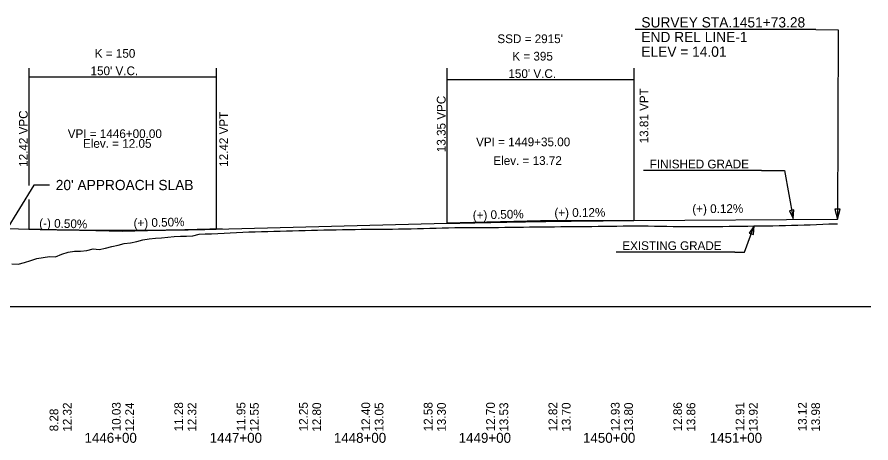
# Model space of a CAD drawing. Extents: x 2360994 to 2383826, y 330623 to 403123.
# Drawn here: x 2369741 to 2370426, y 376763 to 377105 of the extents above; entities that cross this region are included whole.
import ezdxf

# ---------------------------------------------------------------- set-up
doc = ezdxf.new("R2010")
doc.units = 0
for name, color, linetype in [('RD_DDB_GradeTX', 7, 'Continuous'), ('RD_DDB_Profile_EX', 7, 'Continuous'), ('RD_DDB_Profile_Lbl', 7, 'Continuous'), ('RD_DDB_Profile_PR', 7, 'Continuous'), ('RD_DDB_StaTX', 7, 'Continuous'), ('RD_DDB_StripGrade', 7, 'Continuous'), ('RD_DDB_VCLbl', 7, 'Continuous'), ('RD_GPK_Profile_Cell', 7, 'Continuous'), ('RD_TX_Profile', 7, 'Continuous')]:
    doc.layers.add(name, color=color, linetype=linetype)

msp = doc.modelspace()

# ---------------------------------------------------------------- linework, layer by layer
at = {"layer": 'RD_DDB_GradeTX'}
for p, q in [((2370160.57, 376941.5), (2370085.57, 376939.63)), ((2370235.57, 376941.95), (2370160.57, 376941.5)), ((2369825.57, 376933.13), (2369750.57, 376935)), ((2369905.54, 376935.13), (2369825.57, 376933.13))]:
    msp.add_line(p, q, dxfattribs=at)
at = {"layer": 'RD_DDB_Profile_EX'}
for points in [[(2369826.95, 376923.34), (2369831.95, 376923.97), (2369836.95, 376924.99), (2369841.95, 376926.25), (2369846.95, 376927.05), (2369851.95, 376927.63), (2369856.95, 376928.04), (2369861.95, 376928.42), (2369866.95, 376929.06), (2369871.95, 376929.37), (2369876.95, 376929.28), (2369881.95, 376929.67), (2369886.95, 376930.96), (2369891.95, 376931.25), (2369896.95, 376931.23), (2369901.95, 376931.53), (2369906.95, 376931.73), (2369911.95, 376931.98), (2369916.95, 376932.24), (2369921.95, 376932.46), (2369926.95, 376932.68), (2369931.95, 376932.85), (2369936.95, 376933), (2369941.95, 376933.16), (2369946.95, 376933.3), (2369951.95, 376933.44), (2369956.95, 376933.58), (2369961.95, 376933.71), (2369966.95, 376933.84), (2369971.95, 376934), (2369976.95, 376934.16), (2369981.95, 376934.24), (2369986.95, 376934.31), (2369991.95, 376934.41), (2369996.95, 376934.5), (2370001.95, 376934.59), (2370006.95, 376934.68), (2370011.95, 376934.76), (2370016.95, 376934.82), (2370021.95, 376934.87), (2370026.95, 376934.9), (2370031.95, 376934.96), (2370036.95, 376935.01), (2370041.95, 376935.07), (2370046.95, 376935.15), (2370051.95, 376935.23), (2370056.95, 376935.33), (2370061.95, 376935.42), (2370066.95, 376935.56), (2370071.95, 376935.72), (2370076.95, 376935.83), (2370081.95, 376935.96), (2370086.95, 376936.09), (2370091.95, 376936.17), (2370096.95, 376936.22), (2370101.95, 376936.25), (2370106.95, 376936.26), (2370111.95, 376936.28), (2370116.95, 376936.3), (2370121.95, 376936.36), (2370126.95, 376936.41), (2370131.95, 376936.58), (2370136.95, 376936.6), (2370141.95, 376936.63), (2370146.95, 376936.66), (2370151.95, 376936.71), (2370156.95, 376936.76), (2370161.95, 376936.82), (2370166.95, 376936.89), (2370171.95, 376936.94), (2370176.95, 376936.98), (2370181.95, 376937.02), (2370186.95, 376937.06), (2370191.95, 376937.08), (2370196.95, 376937.12), (2370201.95, 376937.17), (2370206.95, 376937.22), (2370211.95, 376937.3), (2370216.95, 376937.39), (2370221.95, 376937.48), (2370226.95, 376937.55), (2370231.95, 376937.6), (2370236.95, 376937.59), (2370241.95, 376937.56), (2370246.95, 376937.49), (2370251.95, 376937.4), (2370256.95, 376937.31), (2370261.95, 376937.25), (2370266.95, 376937.18), (2370271.95, 376937.16), (2370276.95, 376937.19), (2370281.95, 376937.21), (2370286.95, 376937.17), (2370291.95, 376937.17), (2370296.95, 376937.12), (2370301.95, 376937.17), (2370306.95, 376937.21), (2370311.95, 376937.25), (2370316.95, 376937.31), (2370321.95, 376937.38), (2370326.95, 376937.45)], [(2370326.95, 376937.45), (2370331.95, 376937.52), (2370336.95, 376937.56), (2370341.95, 376937.59), (2370346.95, 376937.68), (2370351.95, 376937.8), (2370356.95, 376937.91), (2370361.95, 376938.05), (2370366.95, 376938.18), (2370371.95, 376938.32), (2370376.95, 376938.54), (2370381.95, 376938.7), (2370386.95, 376938.91), (2370391.95, 376939.11), (2370396.95, 376939.22), (2370398.85, 376939.28)], [(2369736.95, 376907.13), (2369741.95, 376906.91), (2369746.95, 376908.24), (2369751.95, 376909.8), (2369756.95, 376911.33), (2369761.95, 376912.3), (2369766.95, 376913.01), (2369771.95, 376912.81), (2369776.95, 376914.82), (2369781.95, 376916.56), (2369786.95, 376917.32), (2369791.95, 376917.17), (2369796.95, 376917.85), (2369801.95, 376919.15), (2369806.95, 376918.63), (2369811.95, 376919.8), (2369816.95, 376921.09), (2369821.95, 376922.2), (2369826.95, 376923.34)]]:
    msp.add_lwpolyline(points, dxfattribs=at)
at = {"layer": 'RD_DDB_Profile_PR'}
for p, q in [((2368940.57, 376955.25), (2369750.57, 376935)), ((2369900.57, 376935), (2370085.57, 376939.63)), ((2370235.57, 376941.95), (2370398.85, 376942.93))]:
    msp.add_line(p, q, dxfattribs=at)
for points in [[(2370085.57, 376939.63), (2370088.57, 376939.7), (2370091.57, 376939.77), (2370094.57, 376939.85), (2370097.57, 376939.92), (2370100.57, 376939.99), (2370103.57, 376940.06), (2370106.57, 376940.12), (2370109.57, 376940.19), (2370112.57, 376940.25), (2370115.57, 376940.32), (2370118.57, 376940.38), (2370121.57, 376940.44), (2370124.57, 376940.5), (2370127.57, 376940.56), (2370130.57, 376940.62), (2370133.57, 376940.68), (2370136.57, 376940.74), (2370139.57, 376940.79), (2370142.57, 376940.85), (2370145.57, 376940.9), (2370148.57, 376940.95), (2370151.57, 376941), (2370154.57, 376941.05), (2370157.57, 376941.1), (2370160.57, 376941.14), (2370163.57, 376941.19), (2370166.57, 376941.24), (2370169.57, 376941.28), (2370172.57, 376941.32), (2370175.57, 376941.36), (2370178.57, 376941.4), (2370181.57, 376941.44), (2370184.57, 376941.48), (2370187.57, 376941.52), (2370190.57, 376941.55), (2370193.57, 376941.59), (2370196.57, 376941.62), (2370199.57, 376941.65), (2370202.57, 376941.68), (2370205.57, 376941.71), (2370208.57, 376941.74), (2370211.57, 376941.77), (2370214.57, 376941.8), (2370217.57, 376941.82), (2370220.57, 376941.85), (2370223.57, 376941.87), (2370226.57, 376941.89), (2370229.57, 376941.91), (2370232.57, 376941.93), (2370235.57, 376941.95)], [(2369750.57, 376935), (2369753.57, 376934.93), (2369756.57, 376934.86), (2369759.57, 376934.79), (2369762.57, 376934.72), (2369765.57, 376934.66), (2369768.57, 376934.6), (2369771.57, 376934.55), (2369774.57, 376934.5), (2369777.57, 376934.45), (2369780.57, 376934.4), (2369783.57, 376934.36), (2369786.57, 376934.32), (2369789.57, 376934.28), (2369792.57, 376934.24), (2369795.57, 376934.21), (2369798.57, 376934.18), (2369801.57, 376934.16), (2369804.57, 376934.14), (2369807.57, 376934.12), (2369810.57, 376934.1), (2369813.57, 376934.09), (2369816.57, 376934.08), (2369819.57, 376934.07), (2369822.57, 376934.06), (2369825.57, 376934.06), (2369828.57, 376934.06), (2369831.57, 376934.07), (2369834.57, 376934.08), (2369837.57, 376934.09), (2369840.57, 376934.1), (2369843.57, 376934.12), (2369846.57, 376934.14), (2369849.57, 376934.16), (2369852.57, 376934.18), (2369855.57, 376934.21), (2369858.57, 376934.24), (2369861.57, 376934.28), (2369864.57, 376934.32), (2369867.57, 376934.36), (2369870.57, 376934.4), (2369873.57, 376934.45), (2369876.57, 376934.5), (2369879.57, 376934.55), (2369882.57, 376934.6), (2369885.57, 376934.66), (2369888.57, 376934.72), (2369891.57, 376934.79), (2369894.57, 376934.86), (2369897.57, 376934.93), (2369900.57, 376935)]]:
    msp.add_spline(points, degree=3, dxfattribs=at)
at = {"layer": 'RD_DDB_VCLbl'}
for p, q in [((2369750.57, 377064.27), (2369750.57, 376969.93)), ((2369900.57, 377064.27), (2369900.57, 376935)), ((2370085.57, 377064.27), (2370085.57, 376939.63)), ((2370235.57, 377064.27), (2370235.57, 376941.95)), ((2369750.57, 377057.33), (2369900.57, 377057.33)), ((2370085.57, 377055.07), (2370235.57, 377055.07)), ((2369750.57, 376958.8), (2369750.57, 376935))]:
    msp.add_line(p, q, dxfattribs=at)
at = {"layer": 'RD_GPK_Profile_Cell'}
msp.add_line((2368825.57, 376872.88), (2370425.57, 376872.88), dxfattribs=at)
at = {"layer": 'RD_TX_Profile'}
for p, q in [((2370381.42, 377095.13), (2370236.53, 377095.13)), ((2370337.77, 376981.97), (2370243.21, 376981.97)), ((2370316.38, 376916.41), (2370221.25, 376916.41))]:
    msp.add_line(p, q, dxfattribs=at)
for points in [[(2370381.42, 377095.13), (2370399.31, 377095.06), (2370398.85, 376942.93)], [(2370337.77, 376981.97), (2370356.17, 376981.97), (2370363.19, 376943.42)], [(2369767.04, 376970.37), (2369754.42, 376970.37), (2369731.52, 376932.84)], [(2370316.38, 376916.41), (2370324.12, 376916.41), (2370331.95, 376937.52)]]:
    msp.add_lwpolyline(points, dxfattribs=at)
for points in [[(2370396.74, 376950.89), (2370398.85, 376942.93), (2370401, 376950.88)], [(2370360.19, 376949.74), (2370363.19, 376943.42), (2370363.76, 376950.39)], [(2370331.3, 376930.55), (2370331.95, 376937.52), (2370327.9, 376931.8)]]:
    msp.add_lwpolyline(points, close=True, dxfattribs=at)

# ---------------------------------------------------------------- texts
at = {"layer": 'RD_DDB_GradeTX'}
for s, rotation, p in [('(+) 0.50%', 1.4321, (2370106.41, 376942.69)), ('(+) 0.12%', 0.34385, (2370171.81, 376944.69)), ('(+) 0.12%', 0.34385, (2370282.4, 376947.79)), ('(+) 0.50%', 1.4321, (2369834.5, 376936.36)), ('(-) 0.50%', 358.5679, (2369758.72, 376936.45))]:
    msp.add_text(s, height=7, rotation=rotation, dxfattribs=at).set_placement(p)
at = {"layer": 'RD_DDB_Profile_Lbl'}
for s, p in [('VPI = 1446+00.00', (2369781.65, 377008.1)), ('Elev. = 12.05', (2369793.88, 377000.26)), ('VPI = 1449+35.00', (2370109.02, 377001.5)), ('Elev. = 13.72', (2370122.88, 376986.5))]:
    msp.add_text(s, height=7, dxfattribs=at).set_placement(p)
at = {"layer": 'RD_DDB_StaTX'}
for s, p in [('1446+00', (2369795.1, 376763.4)), ('1447+00', (2369895.45, 376763.4)), ('1448+00', (2369994.99, 376763.4)), ('1449+00', (2370095.09, 376763.4)), ('1450+00', (2370194.73, 376763.4)), ('1451+00', (2370296.34, 376763.4))]:
    msp.add_text(s, height=8, dxfattribs=at).set_placement(p)
at = {"layer": 'RD_DDB_StripGrade'}
for s, p in [('13.81 VPT', (2370247.12, 377003.84)), ('13.35 VPC', (2370084.57, 376996.78)), ('12.42 VPC', (2369749.57, 376985)), ('12.42 VPT', (2369910.17, 376985)), ('12.32', (2369784.77, 376772.33)), ('10.03', (2369824.1, 376772.63)), ('12.24', (2369834.77, 376772.33)), ('11.28', (2369874.1, 376772.63)), ('12.32', (2369884.77, 376772.33)), ('11.95', (2369924.1, 376772.63)), ('12.55', (2369934.77, 376772.33)), ('12.25', (2369974.1, 376772.63)), ('12.80', (2369984.77, 376772.33)), ('12.40', (2370024.1, 376772.63)), ('13.05', (2370034.77, 376772.33)), ('12.58', (2370074.1, 376772.63)), ('13.30', (2370084.77, 376772.33)), ('12.70', (2370124.1, 376772.63)), ('13.53', (2370134.77, 376772.33)), ('12.82', (2370174.1, 376772.63)), ('13.70', (2370184.77, 376772.33)), ('12.93', (2370224.1, 376772.63)), ('13.80', (2370234.77, 376772.33)), ('12.86', (2370274.1, 376772.63)), ('13.86', (2370284.77, 376772.33)), ('12.91', (2370324.1, 376772.63)), ('13.92', (2370334.77, 376772.33)), ('13.12', (2370374.1, 376772.63)), ('13.98', (2370384.77, 376772.33)), ('8.28', (2369774.1, 376772.63))]:
    msp.add_text(s, height=7, rotation=90, dxfattribs=at).set_placement(p)
at = {"layer": 'RD_DDB_VCLbl'}
for s, p in [("SSD = 2915'", (2370126.09, 377084.32)), ('K = 150', (2369803.32, 377072.58)), ('K = 395', (2370138.05, 377070.32)), ("150' V.C.", (2369799.94, 377058.58)), ("150' V.C.", (2370134.94, 377056.32))]:
    msp.add_text(s, height=7, dxfattribs=at).set_placement(p)
at = {"layer": 'RD_TX_Profile'}
for s, height, p in [('SURVEY STA.1451+73.28', 8.2353, (2370241.53, 377096.89)), ('END REL LINE-1', 8.2353, (2370241.53, 377085.13)), ('ELEV = 14.01', 8.2353, (2370241.53, 377073.36)), ('FINISHED GRADE', 7, (2370248.21, 376983.74)), ("20' APPROACH SLAB", 8.2353, (2369772.04, 376966.26)), ('EXISTING GRADE', 7, (2370226.25, 376918.18))]:
    msp.add_text(s, height=height, dxfattribs=at).set_placement(p)

doc.saveas('drawing.dxf')
